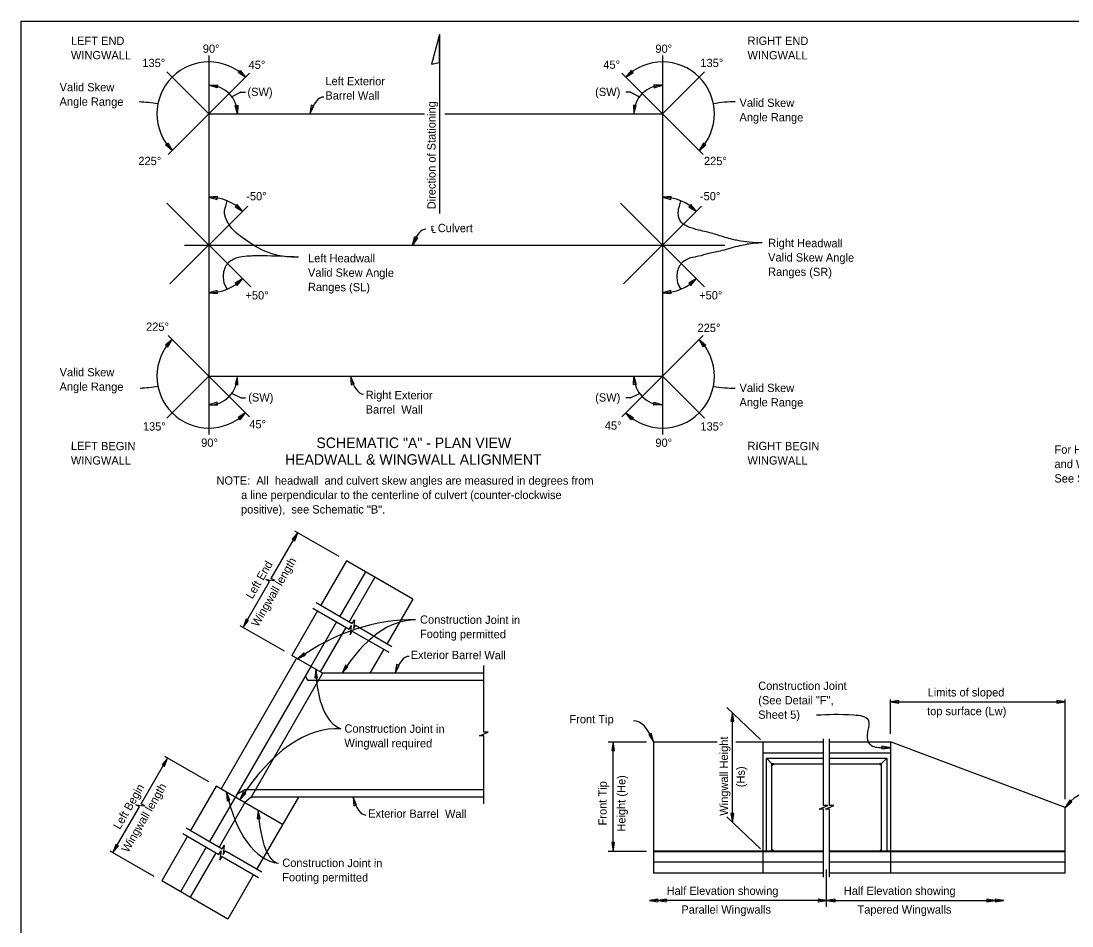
# Model space of a CAD drawing. Extents: x 6 to 291, y -45 to 111.
# Drawn here: x 5.5 to 101.7, y 22.3 to 105.1 of the extents above; entities that cross this region are included whole.
import ezdxf

# ---------------------------------------------------------------- set-up
doc = ezdxf.new("R2010")
doc.units = 0
for name, color, linetype in [('ActivePts-ConstElements', 7, 'Continuous'), ('AdhocPoint_dp', 7, 'Continuous'), ('CL_Minor', 7, 'Continuous'), ('Leader', 7, 'Continuous'), ('PlotBorder_dp', 7, 'Continuous'), ('StrMiscConc', 7, 'Continuous'), ('SubStrConc', 7, 'Continuous'), ('SubStrConc_h', 7, 'Continuous'), ('Symbols', 7, 'Continuous'), ('WallConc', 7, 'Continuous'), ('WallConc_h', 7, 'Continuous')]:
    doc.layers.add(name, color=color, linetype=linetype)

msp = doc.modelspace()

# ---------------------------------------------------------------- linework, layer by layer
at = {"layer": 'ActivePts-ConstElements'}
msp.add_lwpolyline([(5.513, 105.087), (159.887, 105.087), (159.887, 6.648), (5.513, 6.648)], close=True, dxfattribs=at)
at = {"layer": 'AdhocPoint_dp'}
msp.add_lwpolyline([(43.079, 101.128), (43.798, 101.306), (43.798, 103.841)], close=True, dxfattribs=at)
at = {"layer": 'CL_Minor'}
msp.add_line((20.473, 84.593), (69.906, 84.593), dxfattribs=at)
at = {"layer": 'Leader'}
for p, q in [((25.627, 98.577), (24.806, 98.163)), ((25.627, 98.577), (26.064, 98.577)), ((61.267, 98.577), (60.831, 98.577)), ((61.267, 98.577), (62.088, 98.163)), ((25.627, 70.609), (24.806, 71.023)), ((25.627, 70.609), (26.064, 70.609)), ((61.267, 70.609), (60.831, 70.609)), ((61.267, 70.609), (62.088, 71.023)), ((73.148, 39.351), (70.097, 42.278)), ((73.148, 29.351), (70.097, 32.278))]:
    msp.add_line(p, q, dxfattribs=at)
for centre, radius, start, end in [((15.637, 82.611), 15.091, 80.87241, 87.35439), ((70.673, 88.139), 9.545, 88.87567, 100.93206), ((15.64, 86.554), 15.069, 272.89227, 279.13199), ((70.673, 81.048), 9.545, 259.06794, 271.12433)]:
    msp.add_arc(centre, radius, start, end, dxfattribs=at)
for centre, major_axis, ratio, start_param, end_param in [((33.072, 94.105), (0.136, 4.024), 0.38117, 0, 0.917087), ((42.443, 79.132), (-0.102, -6.91), 0.278379, 3.141593, 3.805229), ((36.966, 74.976), (0.136, 4.024), 0.38117, 2.217206, 3.141593), ((40.458, -16.049), (-1.152, -66.355), 0.487106, 3.141593, 3.479813), ((41.944, 17.515), (0.334, -32.792), 0.395503, 3.141593, 3.690686), ((40.871, 42.929), (0.136, 4.024), 0.38117, 0, 0.917087), ((42.395, 60.022), (7.611, 19.697), 0.323358, 2.495768, 3.141593), ((32.09, 1.895), (-2.694, -38.43), 0.393334, 3.141593, 3.759136), ((61.584, 35.367), (0.042, -5.7), 0.42369, 2.289639, 3.1414), ((31.112, 43.047), (2.039, 15.02), 0.467621, 2.235029, 3.141593), ((37.2, 36.466), (0.136, 4.024), 0.38117, 2.217206, 3.141593), ((103.368, 27.495), (-0.033, -7.044), 0.555933, 3.141593, 3.786656), ((31.275, 42.362), (2.202, 14.335), 0.246602, 2.330701, 3.141593)]:
    msp.add_ellipse(centre, major_axis=major_axis, ratio=ratio, start_param=start_param, end_param=end_param, dxfattribs=at)
for points in [[(30.887, 83.477), (29.181, 83.605), (27.813, 84.03), (25.781, 85.259), (25.069, 85.826), (24.414, 86.678), (24.131, 87.54), (24.242, 88.154), (24.368, 88.631)], [(73.305, 84.789), (72.138, 84.842), (71.084, 84.998), (70.591, 85.108), (69.929, 85.291), (68.962, 85.59), (67.713, 85.909), (66.803, 86.162), (65.918, 86.678), (65.635, 87.54), (65.746, 88.154), (65.872, 88.631)], [(73.305, 84.789), (72.629, 84.749), (71.254, 84.519), (70.437, 84.315), (69.633, 84.079), (68.412, 83.809), (67.506, 83.563), (66.803, 83.416), (65.918, 82.899), (65.51, 81.868), (65.668, 80.917), (65.872, 80.555)], [(30.887, 83.477), (27.612, 83.602), (26.209, 83.563), (25.299, 83.416), (24.414, 82.899), (24.006, 81.868), (24.164, 80.917), (24.368, 80.555)], [(78.296, 41.604), (81.705, 41.604), (83.015, 41.143), (82.991, 40.207), (82.916, 39.69), (83.115, 38.997), (83.413, 38.752), (83.954, 38.626), (85.041, 38.59)]]:
    msp.add_spline(points, degree=3, dxfattribs=at)
at = {"layer": 'PlotBorder_dp'}
for p, q in [((43.798, 103.841), (43.798, 87.464)), ((34.608, 56.093), (30.57, 58.425)), ((29.608, 47.433), (25.57, 49.765)), ((85.041, 39.863), (85.041, 43.002)), ((85.041, 42.802), (101.041, 42.802)), ((101.041, 33.888), (101.041, 43.002)), ((70.596, 31.799), (70.596, 41.799)), ((59.216, 39.134), (62.745, 39.134)), ((59.682, 29.134), (59.682, 39.134)), ((22.704, 35.475), (18.666, 37.806)), ((25.498, 34.75), (25.352, 34.498)), ((17.704, 26.814), (13.666, 29.146)), ((59.216, 29.134), (62.745, 29.134)), ((79.207, 24.049), (79.207, 27.459)), ((79.207, 24.621), (62.999, 24.621)), ((79.207, 24.621), (95.416, 24.621))]:
    msp.add_line(p, q, dxfattribs=at)
for points in [[(26.054, 99.956), (25.381, 100.374), (25.556, 100.572)], [(60.84, 99.956), (61.513, 100.374), (61.338, 100.572)], [(22.695, 99.224), (23.487, 99.244), (23.449, 98.982)], [(64.199, 99.224), (63.407, 99.244), (63.445, 98.982)], [(25.326, 96.593), (25.099, 97.352), (25.362, 97.384)], [(31.937, 96.593), (32.307, 97.294), (32.055, 97.376)], [(61.568, 96.593), (61.795, 97.352), (61.532, 97.384)], [(19.334, 93.232), (18.729, 93.744), (18.932, 93.914)], [(67.56, 93.232), (68.165, 93.744), (67.963, 93.914)], [(22.695, 88.964), (23.461, 88.763), (23.485, 89.027)], [(64.199, 88.964), (64.965, 88.763), (64.989, 89.027)], [(25.786, 87.684), (25.274, 88.288), (25.103, 88.086)], [(67.29, 87.684), (66.778, 88.288), (66.607, 88.086)], [(41.338, 84.593), (41.531, 85.361), (41.774, 85.255)], [(25.786, 81.503), (25.106, 81.095), (25.278, 80.894)], [(67.29, 81.503), (66.61, 81.095), (66.782, 80.894)], [(22.695, 80.222), (23.486, 80.171), (23.458, 80.434)], [(64.199, 80.222), (64.99, 80.171), (64.962, 80.434)], [(19.334, 75.954), (18.729, 75.443), (18.932, 75.272)], [(67.56, 75.954), (68.165, 75.443), (67.963, 75.272)], [(25.326, 72.593), (25.099, 71.834), (25.362, 71.802)], [(35.659, 72.593), (35.721, 71.804), (35.978, 71.868)], [(61.568, 72.593), (61.795, 71.834), (61.532, 71.802)], [(22.695, 69.962), (23.487, 69.942), (23.449, 70.204)], [(64.199, 69.962), (63.407, 69.942), (63.445, 70.204)], [(26.054, 69.23), (25.381, 68.812), (25.556, 68.614)], [(60.84, 69.23), (61.513, 68.812), (61.338, 68.614)], [(30.827, 58.276), (30.322, 57.666), (30.551, 57.534)], [(25.827, 49.616), (26.332, 50.226), (26.103, 50.359)], [(30.82, 46.734), (31.536, 47.071), (31.385, 47.288)], [(39.736, 45.417), (40.106, 46.118), (39.855, 46.2)], [(32.484, 45.773), (32.38, 44.988), (32.644, 44.997)], [(34.89, 45.417), (35.419, 46.007), (35.196, 46.148)], [(85.041, 42.802), (85.821, 42.67), (85.821, 42.934)], [(101.041, 42.802), (100.26, 42.934), (100.26, 42.67)], [(70.596, 41.799), (70.464, 41.019), (70.728, 41.019)], [(63.374, 39.134), (63.177, 39.901), (62.935, 39.794)], [(59.682, 39.134), (59.55, 38.353), (59.814, 38.353)], [(85.041, 38.59), (84.264, 38.748), (84.256, 38.484)], [(18.923, 37.658), (18.418, 37.048), (18.647, 36.915)], [(24.325, 34.539), (24.363, 33.748), (24.622, 33.804)], [(25.534, 33.841), (26.07, 34.424), (25.848, 34.568)], [(35.894, 34.084), (35.956, 33.294), (36.212, 33.359)], [(101.041, 33.134), (101.651, 33.639), (101.451, 33.812)], [(27.196, 32.881), (27.125, 32.092), (27.389, 32.113)], [(70.596, 31.799), (70.728, 32.58), (70.464, 32.58)], [(59.682, 29.134), (59.814, 29.915), (59.55, 29.915)], [(13.923, 28.998), (14.428, 29.608), (14.199, 29.74)], [(62.999, 24.621), (63.78, 24.489), (63.78, 24.753)], [(63.78, 24.621), (64.561, 24.489), (64.561, 24.753)], [(79.207, 24.621), (78.426, 24.753), (78.426, 24.489)], [(79.207, 24.621), (79.988, 24.489), (79.988, 24.753)], [(94.635, 24.621), (93.854, 24.753), (93.854, 24.489)], [(95.416, 24.621), (94.635, 24.753), (94.635, 24.489)]]:
    msp.add_lwpolyline(points, close=True, dxfattribs=at)
for centre, radius, start, end in [((22.695, 96.593), 4.753, 45, 225), ((64.199, 96.593), 4.753, 315, 135), ((22.695, 96.593), 2.631, 360, 90), ((64.199, 96.593), 2.631, 90, 180), ((22.695, 84.593), 4.371, 45, 90), ((64.199, 84.593), 4.371, 45, 90), ((22.695, 84.593), 4.371, 270, 315), ((64.199, 84.593), 4.371, 270, 315), ((22.695, 72.593), 4.753, 135, 315), ((64.199, 72.593), 4.753, 225, 45), ((22.695, 72.593), 2.631, 270, 0), ((64.199, 72.593), 2.631, 180, 270)]:
    msp.add_arc(centre, radius, start, end, dxfattribs=at)
at = {"layer": 'StrMiscConc'}
for p, q in [((35.285, 55.702), (32.935, 51.632)), ((41.348, 52.202), (35.285, 55.702)), ((37.017, 54.702), (34.667, 50.632)), ((37.884, 54.202), (35.534, 50.132)), ((41.348, 52.202), (38.998, 48.132)), ((32.635, 51.112), (30.285, 47.042)), ((34.367, 50.112), (32.017, 46.042)), ((35.234, 49.612), (32.884, 45.542)), ((38.698, 47.612), (37.43, 45.417)), ((30.718, 46.792), (23.814, 34.834)), ((33.1, 45.417), (30.285, 47.042)), ((32.017, 46.042), (25.248, 34.317)), ((33.1, 45.417), (26.557, 34.084)), ((47.848, 45.417), (33.1, 45.417)), ((63.374, 39.134), (63.374, 27.134)), ((63.374, 39.134), (69.214, 39.134)), ((70.905, 39.134), (78.924, 39.134)), ((73.374, 39.134), (73.374, 27.134)), ((79.49, 39.134), (85.041, 39.134)), ((85.041, 39.134), (85.041, 27.134)), ((73.707, 29.134), (73.707, 37.634)), ((73.707, 37.634), (74.207, 37.134)), ((73.707, 37.634), (78.924, 37.634)), ((79.49, 37.634), (84.707, 37.634)), ((84.707, 37.634), (84.207, 37.134)), ((84.707, 37.634), (84.707, 29.134)), ((74.207, 36.968), (74.374, 37.134)), ((74.207, 36.968), (74.207, 37.134)), ((74.374, 37.134), (74.207, 37.134)), ((74.207, 29.134), (74.207, 36.968)), ((74.374, 37.134), (78.924, 37.134)), ((79.49, 37.134), (84.041, 37.134)), ((84.041, 37.134), (84.207, 36.968)), ((84.207, 37.134), (84.041, 37.134)), ((84.207, 37.134), (84.207, 36.968)), ((84.207, 36.968), (84.207, 29.134)), ((23.381, 35.084), (21.031, 31.013)), ((29.443, 31.584), (23.381, 35.084)), ((25.248, 34.317), (22.763, 30.013)), ((26.557, 34.084), (25.979, 33.584)), ((47.848, 34.084), (26.557, 34.084)), ((30.887, 34.084), (27.093, 27.513)), ((25.979, 33.584), (23.629, 29.513)), ((20.731, 30.494), (18.381, 26.423)), ((22.463, 29.494), (20.113, 25.423)), ((23.329, 28.994), (20.979, 24.923)), ((74.374, 29.134), (74.207, 29.301)), ((84.207, 29.301), (84.041, 29.134)), ((26.793, 26.994), (24.443, 22.923)), ((78.924, 27.134), (63.374, 27.134)), ((101.041, 27.134), (79.49, 27.134)), ((24.443, 22.923), (18.381, 26.423))]:
    msp.add_line(p, q, dxfattribs=at)
at = {"layer": 'SubStrConc'}
for p, q in [((22.695, 101.918), (22.695, 67.253)), ((64.199, 101.918), (64.199, 67.253)), ((22.695, 96.593), (42.41, 96.593)), ((44.293, 96.593), (64.199, 96.593)), ((22.695, 72.593), (64.199, 72.593)), ((78.924, 29.134), (63.374, 29.134)), ((78.924, 29.072), (63.374, 29.072)), ((101.041, 29.134), (79.49, 29.134)), ((101.041, 29.072), (79.49, 29.072))]:
    msp.add_line(p, q, dxfattribs=at)
at = {"layer": 'SubStrConc_h'}
for p, q in [((22.695, 96.593), (18.857, 100.431)), ((18.984, 92.882), (26.406, 100.305)), ((67.91, 92.882), (60.488, 100.305)), ((64.199, 96.593), (68.037, 100.431)), ((26.532, 80.756), (18.858, 88.43)), ((19.136, 81.035), (26.254, 88.152)), ((68.036, 80.756), (60.362, 88.43)), ((60.641, 81.035), (67.758, 88.152)), ((18.984, 76.305), (26.406, 68.882)), ((67.91, 76.305), (60.488, 68.882)), ((22.695, 72.593), (18.857, 68.755)), ((64.199, 72.593), (68.037, 68.755)), ((31.772, 44.75), (31.522, 45.183)), ((47.848, 44.75), (31.772, 44.75)), ((25.998, 34.75), (25.248, 34.317)), ((47.848, 34.75), (25.998, 34.75))]:
    msp.add_line(p, q, dxfattribs=at)
at = {"layer": 'Symbols'}
for points in [[(25.827, 49.616), (28.243, 53.8), (27.907, 53.994), (28.747, 53.899), (28.411, 54.092), (30.827, 58.276)], [(32.211, 51.357), (35.52, 49.447), (35.714, 49.782), (35.619, 48.943), (35.813, 49.278), (39.15, 47.351)], [(32.511, 51.877), (35.82, 49.966), (36.014, 50.302), (35.919, 49.462), (36.113, 49.798), (39.45, 47.871)], [(47.848, 33.473), (47.848, 39.691), (47.461, 39.691), (48.236, 40.028), (47.848, 40.028), (47.848, 46.131)], [(78.924, 26.748), (78.924, 32.966), (78.537, 32.966), (79.312, 33.303), (78.924, 33.303), (78.924, 39.406)], [(79.49, 26.748), (79.49, 32.966), (79.103, 32.966), (79.877, 33.303), (79.49, 33.303), (79.49, 39.406)], [(13.923, 28.998), (16.338, 33.182), (16.003, 33.375), (16.843, 33.28), (16.507, 33.474), (18.923, 37.658)], [(20.607, 31.258), (23.916, 29.348), (24.11, 29.683), (24.015, 28.843), (24.208, 29.179), (27.546, 27.252)], [(20.307, 30.739), (23.616, 28.828), (23.81, 29.164), (23.715, 28.324), (23.908, 28.659), (27.246, 26.733)]]:
    msp.add_lwpolyline(points, dxfattribs=at)
at = {"layer": 'WallConc'}
for p, q in [((101.041, 33.134), (85.041, 39.134)), ((101.041, 29.134), (101.041, 33.134)), ((101.041, 27.134), (101.041, 29.134))]:
    msp.add_line(p, q, dxfattribs=at)
at = {"layer": 'WallConc_h'}
for p, q in [((73.374, 38.134), (78.924, 38.134)), ((79.49, 38.134), (85.041, 38.134)), ((78.924, 28.134), (63.374, 28.134)), ((101.041, 28.134), (79.49, 28.134))]:
    msp.add_line(p, q, dxfattribs=at)

# ---------------------------------------------------------------- texts
at = {"layer": 'AdhocPoint_dp'}
for s, rotation, p in [('LEFT END', 359.76619, (10.082, 102.912)), ('90°', 359.76619, (22.142, 102.181)), ('90°', 359.76619, (63.544, 102.181)), ('RIGHT END', 359.76619, (71.977, 102.912)), ('WINGWALL', 359.76619, (10.077, 101.592)), ('WINGWALL', 359.76619, (71.972, 101.592)), ('135°', 359.76619, (16.611, 100.879)), ('45°', 359.76619, (26.329, 100.704)), ('45°', 359.76619, (58.78, 100.72)), ('135°', 359.76619, (67.662, 100.879)), ('Left Exterior', 359.76619, (33.36, 99.22)), ('Valid Skew', 359.76619, (9.042, 98.667)), ('Angle Range', 359.76619, (9.037, 97.347)), ('(SW)', 359.76619, (26.225, 98.229)), ('Barrel Wall', 359.76619, (33.355, 97.9)), ('(SW)', 359.76619, (58.036, 98.229)), ('Direction of Stationing', 90, (43.439, 87.858)), ('Valid Skew', 359.76619, (71.243, 97.243)), ('Angle Range', 359.76619, (71.237, 95.923)), ('225°', 359.76619, (16.246, 91.911)), ('225°', 359.76619, (67.991, 91.911)), ('-50°', 359.76619, (26.116, 88.689)), ('-50°', 359.76619, (67.62, 88.689)), ('℄ Culvert', 359.76619, (42.946, 85.776)), ('Right Headwall', 359.76619, (73.867, 84.412)), ('Left Headwall', 359.76619, (31.77, 83.021)), ('Valid Skew Angle', 359.76619, (73.862, 83.092)), ('Valid Skew Angle', 359.76619, (31.764, 81.701)), ('Ranges (SR)', 359.76619, (73.857, 81.772)), ('Ranges (SL)', 359.76619, (31.759, 80.381)), ('+50°', 359.76619, (26.044, 79.618)), ('+50°', 359.76619, (67.548, 79.618)), ('225°', 359.76619, (16.95, 76.747)), ('225°', 359.76619, (67.4, 76.64)), ('Valid Skew', 359.76619, (9.042, 72.59)), ('Angle Range', 359.76619, (9.037, 71.27)), ('Right Exterior', 359.76619, (37.044, 70.498)), ('Valid Skew', 359.76619, (71.243, 71.158)), ('(SW)', 359.76619, (26.298, 70.275)), ('(SW)', 359.76619, (58.036, 70.275)), ('Angle Range', 359.76619, (71.237, 69.838)), ('Barrel  Wall', 359.76619, (37.039, 69.178)), ('135°', 359.76619, (16.663, 67.624)), ('45°', 359.76619, (26.392, 67.82)), ('45°', 359.76619, (58.917, 67.702)), ('135°', 359.76619, (67.662, 67.624)), ('LEFT BEGIN', 359.76619, (10.077, 65.837)), ('90°', 359.76619, (21.993, 66.133)), ('90°', 359.76619, (63.544, 66.133)), ('RIGHT BEGIN', 359.76619, (71.972, 65.837)), ('For Headwall Skew', 359.76619, (100.061, 65.505)), ('WINGWALL', 359.76619, (10.071, 64.517)), ('WINGWALL', 359.76619, (71.967, 64.517)), ('and Wingwall Skews,', 359.76619, (100.056, 64.185)), ('See Schematic "A"', 359.76619, (100.051, 62.865)), ('Wingwall length', 60, (27.192, 49.595)), ('Left End', 60, (26.683, 52.144)), ('Construction Joint in', 359.76619, (42.014, 49.953)), ('Footing permitted', 359.76619, (42.008, 48.633)), ('Exterior Barrel Wall', 359.76619, (41.154, 46.724)), ('Construction Joint in', 359.76619, (35.103, 39.98)), ('Wingwall required', 359.76619, (35.097, 38.66)), ('Wingwall Height', 90, (70.191, 32.376)), ('(Hs)', 90, (71.728, 34.984)), ('Height (He)', 90, (60.809, 30.92)), ('Left Begin', 60, (14.554, 31.063)), ('Wingwall length', 60, (15.313, 28.947)), ('Front Tip', 90, (59.093, 31.491)), ('Exterior Barrel  Wall', 359.76619, (37.273, 32.207)), ('Construction Joint in', 359.76619, (29.412, 27.699)), ('Footing permitted', 359.76619, (29.406, 26.379))]:
    msp.add_text(s, height=0.756, rotation=rotation, dxfattribs=at).set_placement(p)
for s, height, p in [('SCHEMATIC "A" - PLAN VIEW', 0.96, (32.537, 66.017)), ('HEADWALL & WINGWALL ALIGNMENT', 0.96, (29.667, 64.493)), ('NOTE:  All  headwall  and culvert skew angles are measured in degrees from', 0.756, (23.393, 62.668)), ('        a line perpendicular to the centerline of culvert (counter-clockwise', 0.756, (23.393, 61.348)), ('        positive),  see Schematic "B".', 0.756, (23.393, 60.028)), ('Construction Joint', 0.756, (72.955, 43.889)), ('(See Detail "F",', 0.756, (72.955, 42.569)), ('Limits of sloped', 0.756, (88.452, 43.288)), ('top surface (Lw)', 0.756, (88.404, 41.572)), ('Front Tip', 0.756, (55.687, 40.836)), ('Sheet 5)', 0.756, (72.955, 41.249)), ('Half Elevation showing', 0.756, (64.574, 25.135)), ('Half Elevation showing', 0.756, (80.782, 25.135)), ('Parallel Wingwalls', 0.756, (65.923, 23.419)), ('Tapered Wingwalls', 0.756, (82.036, 23.419))]:
    msp.add_text(s, height=height, dxfattribs=at).set_placement(p)

doc.saveas('drawing.dxf')
